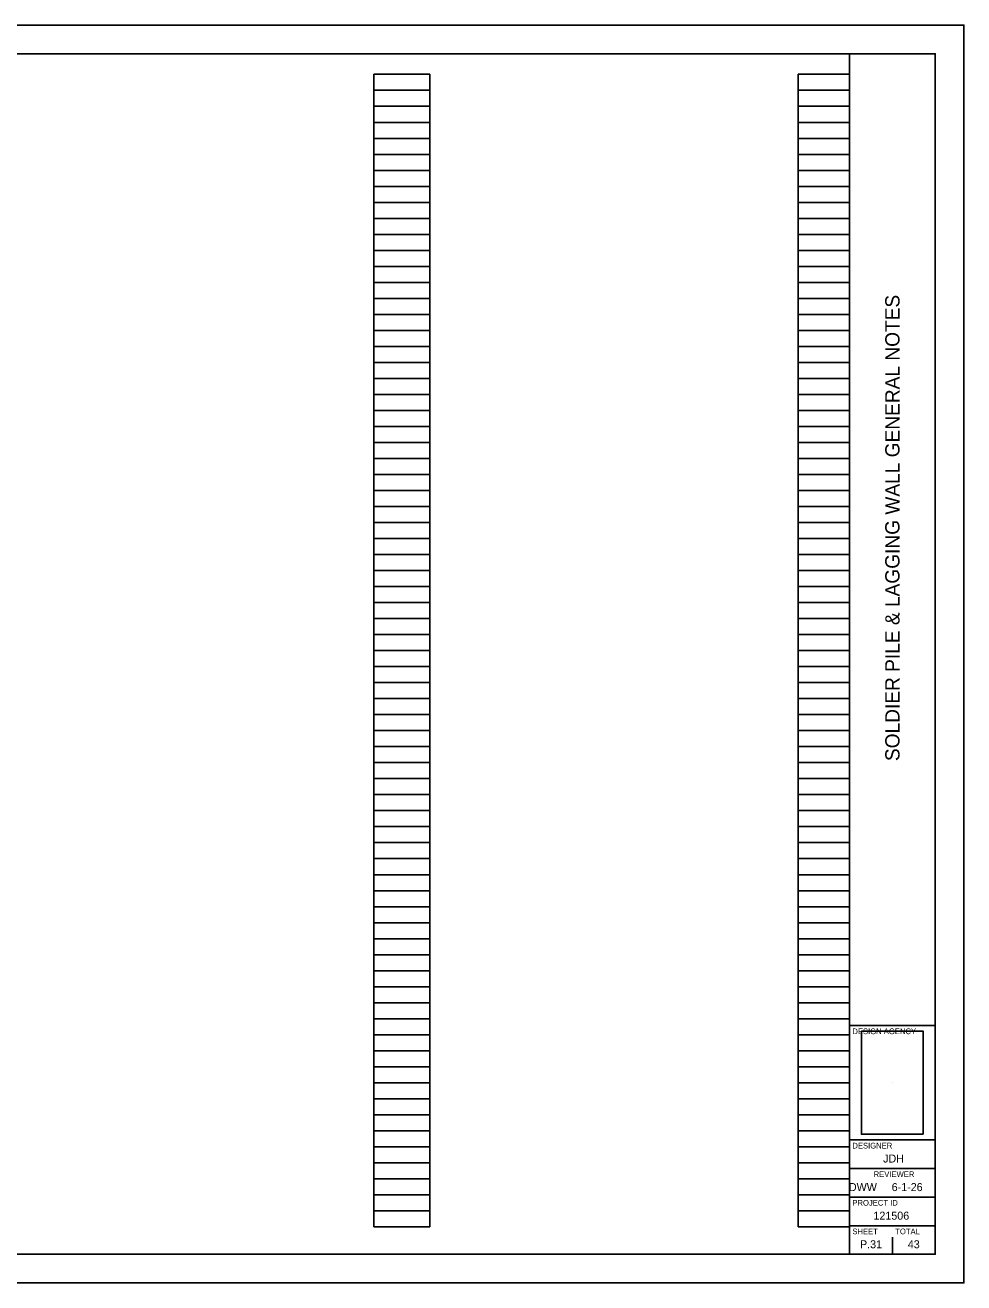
# Model space of a CAD drawing. Extents: x 0 to 34, y 0 to 22.
# Drawn here: x 17.58 to 34, y 0 to 22 of the extents above; entities that cross this region are included whole.
import ezdxf

# ---------------------------------------------------------------- set-up
doc = ezdxf.new("R2010")
doc.units = 0
for name, color, linetype in [('SH_Border', 7, 'Continuous'), ('SH_Cut_Line', 7, 'Continuous'), ('SH_Data', 7, 'Continuous'), ('SH_Text', 7, 'Continuous')]:
    doc.layers.add(name, color=color, linetype=linetype)

msp = doc.modelspace()

# ---------------------------------------------------------------- linework, layer by layer
at = {"layer": 'SH_Border'}
for p, q in [((32, 0.5), (32, 21.5)), ((32, 4.5), (33.5, 4.5)), ((32, 2.5), (33.5, 2.5)), ((32, 2), (33.5, 2)), ((32, 1.5), (33.5, 1.5)), ((32, 1), (33.5, 1))]:
    msp.add_line(p, q, dxfattribs=at)
msp.add_lwpolyline([(1.5, 21.5), (33.5, 21.5), (33.5, 0.5), (1.5, 0.5)], close=True, dxfattribs=at)
at = {"layer": 'SH_Cut_Line'}
msp.add_lwpolyline([(0, 0), (34, 0), (34, 22), (0, 22)], close=True, dxfattribs=at)
at = {"layer": 'SH_Data'}
for p, q in [((23.68, 0.98), (23.68, 21.14)), ((23.68, 21.14), (24.66, 21.14)), ((24.66, 0.98), (24.66, 21.14)), ((31.1, 0.98), (31.1, 21.14)), ((31.1, 21.14), (32, 21.14)), ((32, 0.98), (32, 21.14)), ((23.68, 20.86), (24.66, 20.86)), ((31.1, 20.86), (32, 20.86)), ((23.68, 20.58), (24.66, 20.58)), ((31.1, 20.58), (32, 20.58)), ((23.68, 20.3), (24.66, 20.3)), ((31.1, 20.3), (32, 20.3)), ((23.68, 20.02), (24.66, 20.02)), ((31.1, 20.02), (32, 20.02)), ((23.68, 19.74), (24.66, 19.74)), ((31.1, 19.74), (32, 19.74)), ((23.68, 19.46), (24.66, 19.46)), ((31.1, 19.46), (32, 19.46)), ((23.68, 19.18), (24.66, 19.18)), ((31.1, 19.18), (32, 19.18)), ((23.68, 18.9), (24.66, 18.9)), ((31.1, 18.9), (32, 18.9)), ((23.68, 18.62), (24.66, 18.62)), ((31.1, 18.62), (32, 18.62)), ((23.68, 18.34), (24.66, 18.34)), ((31.1, 18.34), (32, 18.34)), ((23.68, 18.06), (24.66, 18.06)), ((31.1, 18.06), (32, 18.06)), ((23.68, 17.78), (24.66, 17.78)), ((31.1, 17.78), (32, 17.78)), ((23.68, 17.5), (24.66, 17.5)), ((31.1, 17.5), (32, 17.5)), ((23.68, 17.22), (24.66, 17.22)), ((31.1, 17.22), (32, 17.22)), ((23.68, 16.94), (24.66, 16.94)), ((31.1, 16.94), (32, 16.94)), ((23.68, 16.66), (24.66, 16.66)), ((31.1, 16.66), (32, 16.66)), ((23.68, 16.38), (24.66, 16.38)), ((31.1, 16.38), (32, 16.38)), ((23.68, 16.1), (24.66, 16.1)), ((31.1, 16.1), (32, 16.1)), ((23.68, 15.82), (24.66, 15.82)), ((31.1, 15.82), (32, 15.82)), ((23.68, 15.54), (24.66, 15.54)), ((31.1, 15.54), (32, 15.54)), ((23.68, 15.26), (24.66, 15.26)), ((31.1, 15.26), (32, 15.26)), ((23.68, 14.98), (24.66, 14.98)), ((31.1, 14.98), (32, 14.98)), ((23.68, 14.7), (24.66, 14.7)), ((31.1, 14.7), (32, 14.7)), ((23.68, 14.42), (24.66, 14.42)), ((31.1, 14.42), (32, 14.42)), ((23.68, 14.14), (24.66, 14.14)), ((31.1, 14.14), (32, 14.14)), ((23.68, 13.86), (24.66, 13.86)), ((31.1, 13.86), (32, 13.86)), ((23.68, 13.58), (24.66, 13.58)), ((31.1, 13.58), (32, 13.58)), ((23.68, 13.3), (24.66, 13.3)), ((31.1, 13.3), (32, 13.3)), ((23.68, 13.02), (24.66, 13.02)), ((31.1, 13.02), (32, 13.02)), ((23.68, 12.74), (24.66, 12.74)), ((31.1, 12.74), (32, 12.74)), ((23.68, 12.46), (24.66, 12.46)), ((31.1, 12.46), (32, 12.46)), ((23.68, 12.18), (24.66, 12.18)), ((31.1, 12.18), (32, 12.18)), ((23.68, 11.9), (24.66, 11.9)), ((31.1, 11.9), (32, 11.9)), ((23.68, 11.62), (24.66, 11.62)), ((31.1, 11.62), (32, 11.62)), ((23.68, 11.34), (24.66, 11.34)), ((31.1, 11.34), (32, 11.34)), ((23.68, 11.06), (24.66, 11.06)), ((31.1, 11.06), (32, 11.06)), ((23.68, 10.78), (24.66, 10.78)), ((31.1, 10.78), (32, 10.78)), ((23.68, 10.5), (24.66, 10.5)), ((31.1, 10.5), (32, 10.5)), ((23.68, 10.22), (24.66, 10.22)), ((31.1, 10.22), (32, 10.22)), ((23.68, 9.94), (24.66, 9.94)), ((31.1, 9.94), (32, 9.94)), ((23.68, 9.66), (24.66, 9.66)), ((31.1, 9.66), (32, 9.66)), ((23.68, 9.38), (24.66, 9.38)), ((31.1, 9.38), (32, 9.38)), ((23.68, 9.1), (24.66, 9.1)), ((31.1, 9.1), (32, 9.1)), ((23.68, 8.82), (24.66, 8.82)), ((31.1, 8.82), (32, 8.82)), ((23.68, 8.54), (24.66, 8.54)), ((31.1, 8.54), (32, 8.54)), ((23.68, 8.26), (24.66, 8.26)), ((31.1, 8.26), (32, 8.26)), ((23.68, 7.98), (24.66, 7.98)), ((31.1, 7.98), (32, 7.98)), ((23.68, 7.7), (24.66, 7.7)), ((31.1, 7.7), (32, 7.7)), ((23.68, 7.42), (24.66, 7.42)), ((31.1, 7.42), (32, 7.42)), ((23.68, 7.14), (24.66, 7.14)), ((31.1, 7.14), (32, 7.14)), ((23.68, 6.86), (24.66, 6.86)), ((31.1, 6.86), (32, 6.86)), ((23.68, 6.58), (24.66, 6.58)), ((31.1, 6.58), (32, 6.58)), ((23.68, 6.3), (24.66, 6.3)), ((31.1, 6.3), (32, 6.3)), ((23.68, 6.02), (24.66, 6.02)), ((31.1, 6.02), (32, 6.02)), ((23.68, 5.74), (24.66, 5.74)), ((31.1, 5.74), (32, 5.74)), ((23.68, 5.46), (24.66, 5.46)), ((31.1, 5.46), (32, 5.46)), ((23.68, 5.18), (24.66, 5.18)), ((31.1, 5.18), (32, 5.18)), ((23.68, 4.9), (24.66, 4.9)), ((31.1, 4.9), (32, 4.9)), ((23.68, 4.62), (24.66, 4.62)), ((31.1, 4.62), (32, 4.62)), ((23.68, 4.34), (24.66, 4.34)), ((31.1, 4.34), (32, 4.34)), ((23.68, 4.06), (24.66, 4.06)), ((31.1, 4.06), (32, 4.06)), ((23.68, 3.78), (24.66, 3.78)), ((31.1, 3.78), (32, 3.78)), ((23.68, 3.5), (24.66, 3.5)), ((31.1, 3.5), (32, 3.5)), ((32.75, 3.5), (32.75, 3.5)), ((23.68, 3.22), (24.66, 3.22)), ((31.1, 3.22), (32, 3.22)), ((23.68, 2.94), (24.66, 2.94)), ((31.1, 2.94), (32, 2.94)), ((23.68, 2.66), (24.66, 2.66)), ((31.1, 2.66), (32, 2.66)), ((23.68, 2.38), (24.66, 2.38)), ((31.1, 2.38), (32, 2.38)), ((23.68, 2.1), (24.66, 2.1)), ((31.1, 2.1), (32, 2.1)), ((23.68, 1.82), (24.66, 1.82)), ((31.1, 1.82), (32, 1.82)), ((23.68, 1.54), (24.66, 1.54)), ((31.1, 1.54), (32, 1.54)), ((23.68, 1.26), (24.66, 1.26)), ((31.1, 1.26), (32, 1.26)), ((23.68, 0.98), (24.66, 0.98)), ((31.1, 0.98), (32, 0.98)), ((32.375, 0.675), (32.375, 0.675)), ((32.75, 0.5), (32.75, 0.8))]:
    msp.add_line(p, q, dxfattribs=at)
at = {"layer": 'SH_Text'}
msp.add_lwpolyline([(33.291, 2.599), (33.291, 4.401), (32.209, 4.401), (32.209, 2.599)], close=True, dxfattribs=at)

# ---------------------------------------------------------------- texts
at = {"layer": 'SH_Data'}
msp.add_text('SOLDIER PILE & LAGGING WALL GENERAL NOTES', height=0.25, rotation=90, dxfattribs=at).set_placement((32.875, 9.127))
for s, height, p in [('DESIGN AGENCY', 0.1, (32.05, 4.35)), ('DESIGNER', 0.1, (32.05, 2.35)), ('JDH', 0.14, (32.588, 2.105)), ('REVIEWER', 0.1, (32.422, 1.85)), ('DWW', 0.14, (31.99, 1.605)), ('6-1-26', 0.14, (32.738, 1.605)), ('PROJECT ID', 0.1, (32.05, 1.35)), ('121506', 0.14, (32.419, 1.105)), ('SHEET', 0.1, (32.05, 0.85)), ('TOTAL', 0.1, (32.8, 0.85)), ('P.31', 0.14, (32.184, 0.605)), ('43', 0.14, (33.02, 0.605))]:
    msp.add_text(s, height=height, dxfattribs=at).set_placement(p)

doc.saveas('drawing.dxf')
